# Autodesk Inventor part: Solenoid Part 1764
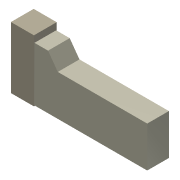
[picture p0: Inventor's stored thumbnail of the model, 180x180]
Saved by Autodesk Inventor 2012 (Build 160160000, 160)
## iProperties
Created: 2010-02
Part Number: Solenoid Part 1764
Document SubType Name: Modeling
Designer: jgehrig
Density: 1 g/cm^3
Material: Default
Author: jgehrig
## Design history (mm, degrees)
sketch "Sketch1"
  geometry: L1 (-36.62, 6.235)-(-25.825, 6.235); L2 (-25.825, 6.235)-(-25.825, -22.34); L3 (-25.825, -22.34)-(-36.62, -22.34); L4 (-36.62, -22.34)-(-36.62, 6.235); L5 (-25.825, 3.06)-(-19.475, 3.06); L6 (-19.475, 3.06)-(-14.915, -3.29); L7 (-14.915, -3.29)-(26.995, -3.29); L8 (26.995, -3.29)-(26.995, -22.34); L9 (26.995, -22.34)-(-25.825, -22.34); 1 further point
  constraints: 18 end point, 4 parallel, 3 perpendicular, 1 horizontal, 1 point on line
  dimensions: "d0" = 28.575 distance of L3.end L1.start; "d1" = 10.795 distance of L1.start L1.end; "d2" = 25.4 distance between parallel lines of L9 L5; "d3" = 19.05 distance of L7.end L8.end; "d4" = 41.91 distance of L6.end L7.end; "d5" = 6.35 distance of L5.start L5.end
extrude "Extrusion1" new body sketch "Sketch1" distance "d6" = 10.16; taper "d7" = 0 deg
sketch "Sketch2"
  geometry: L1 (36.62, -22.34)-(-26.995, -22.34) reference; L2 (36.62, 6.235)-(25.825, 6.235); L3 (25.825, 6.235)-(25.825, -22.34); L4 (25.825, -22.34)-(36.62, -22.34); L5 (36.62, -22.34)-(36.62, 6.235); 1 further point
  constraints: 8 end point, 2 parallel, 1 horizontal, 1 perpendicular, 1 point on line
extrude "Extrusion2" join sketch "Sketch2" distance "d8" = 0.254; taper "d9" = 0 deg
sketch "Sketch3"
  geometry: L1 (26.995, -22.34)-(-36.62, -22.34) reference; L2 (-36.62, 6.235)-(-25.825, 6.235); L3 (-25.825, 6.235)-(-25.825, -22.34); L4 (-25.825, -22.34)-(-36.62, -22.34); L5 (-36.62, -22.34)-(-36.62, 6.235); 1 further point
  constraints: 8 end point, 2 parallel, 1 horizontal, 1 perpendicular, 1 point on line
extrude "Extrusion3" join sketch "Sketch3" distance "d10" = 0.254; taper "d11" = 0 deg
sketch "Sketch4"
  geometry: L1 (-10.795, 10.414)-(0, 10.414); L2 (0, 10.414)-(0, -0.254); L3 (0, -0.254)-(-10.795, -0.254); L4 (-10.795, -0.254)-(-10.795, 10.414); 1 further point
  constraints: 8 end point, 2 parallel, 1 horizontal, 1 perpendicular
extrude "Extrusion4" join sketch "Sketch4" distance "d12" = 0.254; taper "d13" = 0 deg
body "Solid1"
